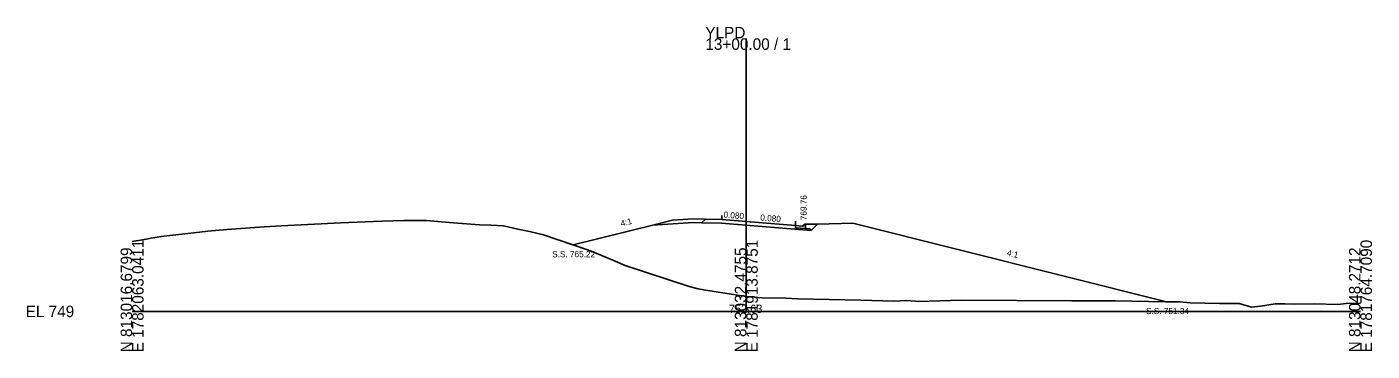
# Model space of a CAD drawing. Extents: x -26 to 353, y -10 to 9080.
# Drawn here: x -25.7 to 302.8, y 2990.3 to 3069.4 of the extents above; entities that cross this region are included whole.
import ezdxf

# ---------------------------------------------------------------- set-up
doc = ezdxf.new("R2010")
doc.units = 0
for name, color, linetype in [('Exist Cross Section Cell', 7, 'Continuous'), ('Exist XS Center Line Elevation Label', 7, 'Continuous'), ('Exist XS Ground Line', 7, 'Continuous'), ('Prop XS Dump Level', 7, 'Continuous'), ('Prop XS Earthwork Shape', 7, 'Continuous'), ('Prop XS EOT Tick Mark', 7, 'Continuous'), ('Prop XS Finish Grade', 7, 'Continuous'), ('Prop XS Finish Grade CurbGutter', 7, 'Continuous'), ('Prop XS Finish Grade Earthwork', 7, 'Continuous'), ('Prop XS Finish Grade Paved Shoulder', 7, 'Continuous'), ('Prop XS Finish Grade Pavement', 7, 'Continuous'), ('Prop XS Hydro Elevations', 7, 'Continuous'), ('Prop XS Pvmt Edge Slope', 7, 'Continuous'), ('Prop XS SE Text', 7, 'Continuous'), ('Prop XS Side Slope Text', 7, 'Continuous'), ('Prop XS SS Elevation Text', 7, 'Continuous'), ('Prop XS Subgrade CurbGutter', 7, 'Continuous'), ('Prop XS Subgrade Earthwork', 7, 'Continuous'), ('Scratch_Level_3', 7, 'Continuous')]:
    doc.layers.add(name, color=color, linetype=linetype)

msp = doc.modelspace()

# ---------------------------------------------------------------- linework, layer by layer
at = {"layer": 'Exist Cross Section Cell'}
for p, q in [((150, 3000), (150, 3066.65)), ((0, 3000), (150, 3000)), ((150, 3000), (300, 3000))]:
    msp.add_line(p, q, dxfattribs=at)
at = {"layer": 'Exist XS Ground Line'}
for p, q in [((15.07, 3019.2), (18.49, 3019.58)), ((18.49, 3019.58), (23.17, 3019.97)), ((23.17, 3019.97), (32.27, 3020.67)), ((32.27, 3020.67), (35.02, 3020.83)), ((35.02, 3020.83), (36.38, 3020.9)), ((36.38, 3020.9), (46.21, 3021.4)), ((46.21, 3021.4), (50.88, 3021.63)), ((50.88, 3021.63), (60.95, 3022.02)), ((60.95, 3022.02), (66.38, 3022.21)), ((66.38, 3022.21), (69.2, 3022.22)), ((69.2, 3022.22), (71.89, 3022.22)), ((71.89, 3022.22), (77.47, 3021.68)), ((77.47, 3021.68), (84.82, 3021.16)), ((84.82, 3021.16), (87.73, 3021.06)), ((87.73, 3021.06), (90.67, 3020.85)), ((90.67, 3020.85), (94.2, 3020.1)), ((94.2, 3020.1), (97.02, 3019.47)), ((97.02, 3019.47), (100.48, 3018.67)), ((0, 3017.09), (2.5, 3017.49)), ((2.5, 3017.49), (5.58, 3018.01)), ((5.58, 3018.01), (7.71, 3018.36)), ((7.71, 3018.36), (15.07, 3019.2)), ((100.48, 3018.67), (111.23, 3015.04)), ((111.23, 3015.04), (112.56, 3014.56)), ((112.56, 3014.56), (117.41, 3012.47)), ((117.41, 3012.47), (120.42, 3011.21)), ((120.42, 3011.21), (136.04, 3006.09)), ((136.04, 3006.09), (138.21, 3005.47)), ((138.21, 3005.47), (139.51, 3005.27)), ((139.51, 3005.27), (150, 3003.63)), ((150, 3003.63), (153.91, 3003.33)), ((153.91, 3003.33), (159.67, 3003.22)), ((159.67, 3003.22), (162.53, 3003.09)), ((162.53, 3003.09), (177.99, 3002.71)), ((177.99, 3002.71), (186.04, 3002.47)), ((186.04, 3002.47), (189.09, 3002.66)), ((189.09, 3002.66), (191.33, 3002.46)), ((191.33, 3002.46), (191.98, 3002.39)), ((191.98, 3002.39), (202.59, 3002.73)), ((202.59, 3002.73), (229.49, 3002.6)), ((229.49, 3002.6), (240.06, 3002.58)), ((240.06, 3002.58), (252.38, 3002.34)), ((252.38, 3002.34), (255.9, 3002.37)), ((255.9, 3002.37), (258.44, 3002.11)), ((258.44, 3002.11), (265.54, 3001.89)), ((265.54, 3001.89), (270.38, 3001.93)), ((270.38, 3001.93), (273.35, 3001.07)), ((273.35, 3001.07), (275.56, 3001.3)), ((275.56, 3001.3), (279.17, 3001.82)), ((279.17, 3001.82), (281.6, 3001.83)), ((281.6, 3001.83), (283.97, 3001.77)), ((283.97, 3001.77), (288.66, 3001.87)), ((288.66, 3001.87), (294.48, 3001.7)), ((294.48, 3001.7), (296.53, 3001.95)), ((296.53, 3001.95), (300, 3002.03))]:
    msp.add_line(p, q, dxfattribs=at)
at = {"layer": 'Prop XS Dump Level'}
for p, q in [((144, 3022.44), (150, 3021.96)), ((150, 3021.96), (162, 3021))]:
    msp.add_line(p, q, dxfattribs=at)
at = {"layer": 'Prop XS Earthwork Shape'}
msp.add_lwpolyline([(127.17, 3021.08), (107.74, 3016.22), (111.23, 3015.04), (112.56, 3014.56), (117.41, 3012.47), (120.42, 3011.21), (136.04, 3006.09), (138.21, 3005.47), (139.51, 3005.27), (150, 3003.63), (153.91, 3003.33), (159.67, 3003.22), (162.53, 3003.09), (177.99, 3002.71), (186.04, 3002.47), (189.09, 3002.66), (191.33, 3002.46), (191.98, 3002.39), (202.59, 3002.73), (229.49, 3002.6), (240.06, 3002.58), (252.38, 3002.34), (252.65, 3002.34), (176, 3021.5), (167.39, 3021.32), (165.84, 3019.78), (149.93, 3021.05), (143.95, 3021.53), (139.1, 3021.62), (137.02, 3021.67)], close=True, dxfattribs=at)
at = {"layer": 'Prop XS EOT Tick Mark'}
for p, q in [((144, 3022.44), (144, 3023.44)), ((162, 3021), (162, 3022))]:
    msp.add_line(p, q, dxfattribs=at)
at = {"layer": 'Prop XS Finish Grade'}
for p, q in [((137, 3022.58), (132, 3022.28)), ((140, 3022.52), (137, 3022.58)), ((132, 3022.28), (127.17, 3021.08)), ((164.5, 3021.26), (167.39, 3021.32))]:
    msp.add_line(p, q, dxfattribs=at)
at = {"layer": 'Prop XS Finish Grade CurbGutter'}
for p, q in [((162, 3021), (163.75, 3020.79)), ((163.75, 3020.79), (163.88, 3020.82)), ((163.88, 3020.82), (163.97, 3020.91)), ((163.97, 3020.91), (164.03, 3021.16)), ((164.03, 3021.16), (164.13, 3021.25)), ((164.25, 3021.26), (164.13, 3021.25)), ((164.5, 3021.26), (164.25, 3021.26))]:
    msp.add_line(p, q, dxfattribs=at)
at = {"layer": 'Prop XS Finish Grade Earthwork'}
for p, q in [((127.17, 3021.08), (107.74, 3016.22)), ((167.39, 3021.32), (176, 3021.5)), ((176, 3021.5), (252.65, 3002.34))]:
    msp.add_line(p, q, dxfattribs=at)
at = {"layer": 'Prop XS Finish Grade Paved Shoulder'}
msp.add_line((144, 3022.44), (140, 3022.52), dxfattribs=at)
at = {"layer": 'Prop XS Finish Grade Pavement'}
for p, q in [((144, 3022.44), (150, 3021.96)), ((150, 3021.96), (162, 3021))]:
    msp.add_line(p, q, dxfattribs=at)
at = {"layer": 'Prop XS Pvmt Edge Slope'}
for p, q in [((140, 3022.52), (139.1, 3021.62)), ((164.5, 3020.22), (165.5, 3020.14)), ((165.5, 3020.14), (165.84, 3019.78))]:
    msp.add_line(p, q, dxfattribs=at)
at = {"layer": 'Prop XS Subgrade CurbGutter'}
for p, q in [((162, 3021), (162, 3020.42)), ((162, 3020.42), (164.5, 3020.22)), ((164.5, 3020.22), (164.5, 3021.26))]:
    msp.add_line(p, q, dxfattribs=at)
at = {"layer": 'Prop XS Subgrade Earthwork'}
for p, q in [((137.02, 3021.67), (127.17, 3021.08)), ((139.1, 3021.62), (137.02, 3021.67)), ((143.95, 3021.53), (139.1, 3021.62)), ((143.95, 3021.53), (149.93, 3021.05)), ((149.93, 3021.05), (165.84, 3019.78)), ((165.84, 3019.78), (167.39, 3021.32))]:
    msp.add_line(p, q, dxfattribs=at)
at = {"layer": 'Scratch_Level_3'}
for p, q in [((137, 3022.58), (132, 3022.28)), ((140, 3022.52), (137, 3022.58)), ((139.1, 3021.62), (140, 3022.52)), ((132, 3022.28), (127.17, 3021.08)), ((127.17, 3021.08), (137.02, 3021.67)), ((137.02, 3021.67), (139.1, 3021.62))]:
    msp.add_line(p, q, dxfattribs=at)

# ---------------------------------------------------------------- texts
at = {"layer": 'Exist Cross Section Cell'}
for s, p in [('YLPD', (140, 3066.65)), ('13+00.00 / 1', (140, 3063.85)), ('EL 749', (-26, 2998.6))]:
    msp.add_text(s, height=2.8, dxfattribs=at).set_placement(p)
for s, p in [('E 1782063.0411', (2.8, 2990)), ('E 1781913.8751', (152.8, 2990)), ('E 1781764.7090', (302.8, 2990)), ('N 813016.6799', (0, 2990)), ('N 813032.4755', (150, 2990)), ('N 813048.2712', (300, 2990))]:
    msp.add_text(s, height=2.8, rotation=90, dxfattribs=at).set_placement(p)
at = {"layer": 'Exist XS Center Line Elevation Label'}
msp.add_text('752.63', height=2, dxfattribs=at).set_placement((145.75, 2999.63))
at = {"layer": 'Prop XS Dump Level'}
msp.add_text('Case4', height=0.04, dxfattribs=at).set_placement((132, 3022.24))
at = {"layer": 'Prop XS Hydro Elevations'}
msp.add_text('769.76', height=1.5, rotation=90, dxfattribs=at).set_placement((164.75, 3022.26))
at = {"layer": 'Prop XS SE Text'}
for p in [(144.38, 3022.91), (153.38, 3022.19)]:
    msp.add_text('0.080', height=1.5, rotation=355.4261, dxfattribs=at).set_placement(p)
at = {"layer": 'Prop XS Side Slope Text'}
for rotation, p in [(14.0362, (119.51, 3020.71)), (345.9638, (213.54, 3013.67))]:
    msp.add_text('4:1', height=1.5, rotation=rotation, dxfattribs=at).set_placement(p)
at = {"layer": 'Prop XS SS Elevation Text'}
for s, p in [('S.S. 765.22', (102.59, 3013.22)), ('S.S. 751.34', (247.64, 2999.34))]:
    msp.add_text(s, height=1.5, dxfattribs=at).set_placement(p)

doc.saveas('drawing.dxf')
